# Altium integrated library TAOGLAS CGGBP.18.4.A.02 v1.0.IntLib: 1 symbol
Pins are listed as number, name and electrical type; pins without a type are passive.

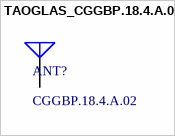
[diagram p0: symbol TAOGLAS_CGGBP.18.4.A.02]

## TAOGLAS_CGGBP.18.4.A.02
designator ANT?, comment CGGBP.18.4.A.02
18mm*18mm*4mm GPS/GLONASS/Galleo/BeiDou Embedded Patch Antenna GPS-Galileo 1575MHz / BeiDou 1561MHz / GLONASS 1602MHz; ComponentLibStatus: Created; MFG: Taoglas; Temp_High: +85C; Temp_Low: -40C
footprint TAOGLAS_CGGBP.18.4.A.02 (18mm*18mm*4mm GPS/GLONASS/Galleo/BeiDou Embedded Patch Antenna GPS-Galileo 1575MHz / BeiDou 1561MHz / GLONASS 1602MHz)
pins: 1 RF Feed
